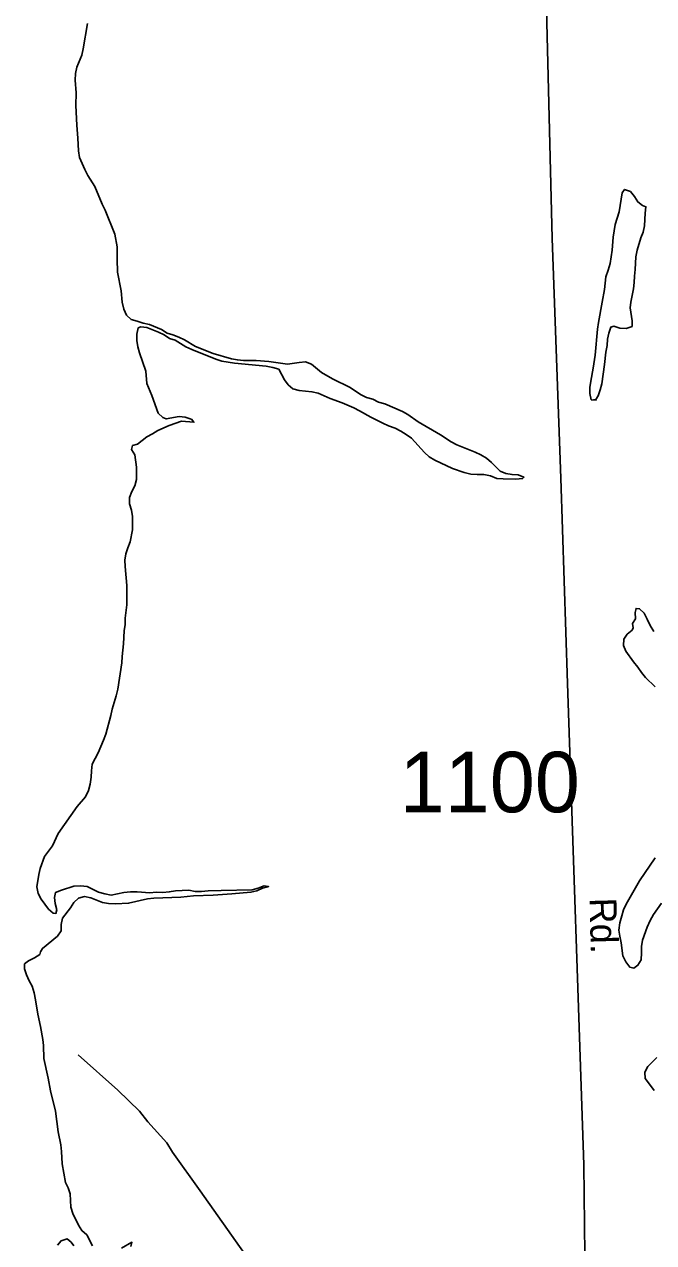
# Model space of a CAD drawing. Extents: x 1945482 to 2853149, y 66427 to 1015778.
# Drawn here: x 2325507 to 2327042, y 117706 to 120678 of the extents above; entities that cross this region are included whole.
import ezdxf

# ---------------------------------------------------------------- set-up
doc = ezdxf.new("R2010")
doc.units = 0
for name, color, linetype in [('Old_Level_11', 7, 'Continuous'), ('Old_Level_32', 7, 'Continuous'), ('Old_Level_35', 7, 'Continuous'), ('Old_Level_60', 7, 'Continuous'), ('Old_Level_8', 7, 'Continuous')]:
    doc.layers.add(name, color=color, linetype=linetype)

msp = doc.modelspace()

# ---------------------------------------------------------------- linework, layer by layer
at = {"layer": 'Old_Level_32'}
msp.add_lwpolyline([(2327467.5, 115613), (2327216.3, 115990), (2327054, 116232.6), (2327006.9, 116309.4), (2326966.8, 116386.2), (2326929.9, 116468.6), (2326914.2, 116526.2), (2326903.7, 116604.7), (2326893.2, 116772.3), (2326885.4, 117136.2), (2326877, 117384.2), (2326871.6, 117896.1), (2326831.4, 119069.9), (2326815.4, 119571.1), (2326794, 120155.3), (2326772.5, 121045)], dxfattribs=at)
at = {"layer": 'Old_Level_35'}
msp.add_lwpolyline([(2326978.1, 116346.6), (2326652.6, 116809.3), (2326394.8, 117178.8), (2326165.5, 117508.5), (2325936.1, 117832.3), (2325869, 117927.4), (2325854.7, 117949.5), (2325808.4, 118000.8), (2325788, 118026.9), (2325735.4, 118078.4), (2325638.5, 118164.1)], dxfattribs=at)
at = {"layer": 'Old_Level_60'}
for points in [[(2325767.7, 119957.9), (2325756.5, 119969), (2325750.2, 119983.1), (2325745.7, 120000), (2325743.2, 120028.2), (2325734.5, 120073.8), (2325733.5, 120104.9), (2325733.7, 120135.7), (2325727.7, 120166.2), (2325704.2, 120224.4), (2325697, 120239.1), (2325679, 120282.4), (2325662.2, 120309.7), (2325654.7, 120323.6), (2325641.5, 120353.3), (2325639.2, 120369.4), (2325637.7, 120400.4), (2325635, 120431.9), (2325633, 120479.7), (2325633.7, 120511), (2325631.5, 120542.1), (2325632, 120558.2), (2325635, 120573.3), (2325647.2, 120602.9), (2325651, 120618.6), (2325661.2, 120680.5)], [(2326902.2, 119761.2), (2326889.5, 119762.4), (2326886.5, 119777.2), (2326886.5, 119792.5), (2326888.2, 119807.9), (2326894.2, 119839.6), (2326899, 119871.3), (2326904.7, 119934.3), (2326907, 119950.7), (2326916.2, 120000), (2326921.5, 120031.3), (2326925.2, 120062.5), (2326931, 120078.1), (2326935.5, 120094.3), (2326940.5, 120127), (2326943.2, 120159.3), (2326948, 120189.8), (2326958, 120220.5), (2326964.7, 120267.1), (2326971, 120275.5), (2326985.2, 120270.1), (2326994.7, 120258.3), (2327003.2, 120245), (2327014.5, 120236.2), (2327023, 120233.1), (2327020.7, 120217.4), (2327019.7, 120186.5), (2327016.2, 120171.2), (2327010.7, 120157), (2327001.2, 120127), (2326998.2, 120111.1), (2326997, 120079.8), (2326994.7, 120064), (2326994.5, 120048.6), (2326993, 120033), (2326986, 120000), (2326984.2, 119986.6), (2326989.5, 119955), (2326989.2, 119941.3), (2326974.5, 119935.9), (2326959.2, 119936.7), (2326944.7, 119941.5), (2326937.2, 119939.6), (2326932.5, 119924.5), (2326929.2, 119909.8), (2326928, 119894.3), (2326925, 119878.6), (2326921.7, 119848.2), (2326915, 119801.2), (2326911.7, 119786.3), (2326906.5, 119772), (2326901, 119762.6), (2326895.5, 119762.5), (2326902.2, 119761.2)], [(2325577.5, 118509.9), (2325566, 118520), (2325548.5, 118544.5), (2325541, 118557.8), (2325537.7, 118573.9), (2325542.7, 118604.4), (2325546, 118619.1), (2325556.5, 118648.2), (2325575.7, 118673.9), (2325590, 118704.2), (2325636, 118769.9), (2325656.2, 118793.8), (2325663.5, 118808.9), (2325668, 118825), (2325670.7, 118841.5), (2325671, 118857.4), (2325673, 118873.4), (2325687.5, 118900.9), (2325700.7, 118931.6), (2325706, 118946.6), (2325718.5, 118992.1), (2325721.5, 119007.9), (2325731, 119039.9), (2325735, 119056.4), (2325745.5, 119120.9), (2325745.7, 119136.4), (2325749, 119167.2), (2325751, 119198.8), (2325753, 119214.3), (2325753.2, 119229.8), (2325757, 119261.9), (2325757, 119309.2), (2325753, 119355.6), (2325752.5, 119371), (2325755, 119386.3), (2325759.7, 119401.2), (2325765.7, 119415.4), (2325771, 119445.4), (2325771, 119477.7), (2325768.7, 119493), (2325764, 119508.6), (2325764, 119524.3), (2325769.5, 119538.5), (2325777, 119552.1), (2325780.7, 119567.5), (2325780.5, 119598), (2325777.2, 119627.8), (2325768.7, 119640.9), (2325771.5, 119650.4), (2325783.5, 119654), (2325806.2, 119672.1), (2325819.7, 119679.1), (2325832.5, 119687.7), (2325860.5, 119699.8), (2325890.2, 119709.7), (2325921, 119707.5), (2325914.7, 119714.6), (2325914.2, 119715.1), (2325899.7, 119719.8), (2325884.5, 119721.3), (2325853.5, 119715.7), (2325845, 119718.9), (2325834, 119729.8), (2325818.5, 119772.9), (2325806.2, 119801.7), (2325803.5, 119832.2), (2325788.5, 119876.8), (2325784.5, 119891.3), (2325782, 119906.8), (2325781.5, 119922.5), (2325785, 119937.4), (2325791.2, 119939.9)], [(2325767.7, 119957.9), (2325782.8, 119954.3), (2325797.5, 119949.4), (2325812.5, 119946.2), (2325841.5, 119933.3), (2325855.5, 119925.1), (2325869.7, 119920.5), (2325883.7, 119914.8), (2325897.5, 119908.1), (2325924.5, 119892.1), (2325967.7, 119874.9), (2326012.2, 119862.2), (2326027, 119859.5), (2326042, 119858.4), (2326072.7, 119858.4), (2326103.7, 119855.5), (2326149, 119848.9), (2326177.7, 119853.4), (2326192.7, 119854.9), (2326207.2, 119848.8), (2326231.7, 119828.6), (2326258.5, 119813.1), (2326301.7, 119792.6), (2326327, 119774.9), (2326341.7, 119767.8), (2326356.7, 119763.8), (2326371.2, 119756.8), (2326386, 119752.2), (2326429, 119733.6), (2326442.7, 119726.7), (2326467.5, 119708.3), (2326521.7, 119677), (2326548.2, 119659.4), (2326562, 119652.1), (2326606.2, 119634.5), (2326620.7, 119627.7), (2326634, 119619.7), (2326646, 119609.3), (2326667.5, 119587.9), (2326681.7, 119582.7), (2326696.5, 119579.7), (2326711.5, 119579.5), (2326725.5, 119573.2), (2326724, 119571.9), (2326722, 119570.2), (2326705.7, 119568.6), (2326674.7, 119569.2), (2326659, 119570.3), (2326644, 119576.5), (2326628, 119579.9), (2326611.7, 119579.9), (2326596, 119580.9), (2326580, 119585), (2326551.2, 119594.6), (2326508, 119614.7), (2326494.5, 119622.9), (2326483, 119633.4), (2326451, 119668.8), (2326438.7, 119677.6), (2326425, 119686.1), (2326411.5, 119693), (2326395.5, 119698.8), (2326381.2, 119705.6), (2326352.5, 119719.8), (2326324.5, 119735.7), (2326310.5, 119742.8), (2326282.2, 119755), (2326253, 119765.3), (2326224, 119778.3), (2326208.5, 119782), (2326177.2, 119784.8), (2326162, 119788.7), (2326151, 119798.9), (2326141.5, 119811.2), (2326127.7, 119836.8), (2326113, 119841.3), (2326097, 119844.3), (2326019.5, 119851.7), (2325989.2, 119856.5), (2325974, 119861), (2325915.5, 119884.9), (2325901.5, 119891.5), (2325875.5, 119907.6), (2325861, 119911.6), (2325848.5, 119920.3), (2325834.5, 119927.2), (2325806.2, 119938.9), (2325791.2, 119939.9)], [(2327045.7, 119062.1), (2327022.2, 119085.2), (2327012.2, 119097.3), (2327003.5, 119110), (2326993, 119122.7), (2326973.7, 119149.1), (2326968.2, 119163.2), (2326969, 119178.4), (2326977.2, 119190.5), (2326989, 119200.5), (2326991.5, 119205.9), (2326990.2, 119216.8), (2326997.5, 119228.3), (2326997, 119243.5), (2326999, 119253.3), (2327007.5, 119252.4), (2327018.5, 119241.9), (2327026.2, 119227.1), (2327033, 119211.8), (2327042, 119197)], [(2326993.5, 118375.5), (2326983.5, 118378.4), (2326974, 118391.3), (2326966.7, 118406.2), (2326962.7, 118437.9), (2326959, 118453.5), (2326957, 118468.6), (2326959.5, 118486), (2326964, 118503.1), (2326968.5, 118518), (2326974.5, 118532.1), (2327007.5, 118588.9), (2327045.5, 118645.1)], [(2325577.5, 118509.9), (2325584, 118509.1), (2325586.5, 118518.5), (2325582.2, 118533.5), (2325580.7, 118548.6), (2325583.5, 118560.4), (2325597.7, 118566.4), (2325628.2, 118575.7), (2325644, 118576.6), (2325660.5, 118574.8), (2325688.5, 118561.6), (2325704, 118557.3), (2325719.2, 118554.2), (2325750, 118560.1), (2325766.5, 118562.3), (2325782.2, 118562.1), (2325813.5, 118559.5), (2325828.7, 118560.8), (2325845, 118560.4), (2325860.7, 118562), (2325876.2, 118564.7), (2325908.2, 118565.8), (2325924, 118562.8), (2325939, 118562.5), (2325955.2, 118564.2), (2325987, 118565.5), (2326063, 118566.7), (2326077.7, 118571), (2326092, 118576.3), (2326102.7, 118575), (2326100.5, 118574.4), (2326088, 118571), (2326074.5, 118564.1), (2326060, 118561), (2326013.5, 118557.1), (2325967.5, 118554.1), (2325920, 118552.1), (2325889, 118549.3), (2325823, 118546.6), (2325808, 118544.7), (2325761.5, 118534.1), (2325729.5, 118533), (2325713, 118533.8), (2325698, 118536.3), (2325669.2, 118547.7), (2325654, 118550.8), (2325639.2, 118546.4), (2325627.7, 118536.1), (2325620.2, 118523), (2325600.5, 118498.1), (2325597.2, 118482.5), (2325597, 118466.9), (2325588, 118454.2), (2325551.7, 118424.2), (2325547, 118415.9), (2325545.2, 118409.2), (2325532, 118400.8), (2325517.5, 118393.9), (2325507.5, 118386.1)], [(2327060.5, 118534.2), (2327041.5, 118506.9), (2327033.2, 118492), (2327026.2, 118476.2), (2327014.5, 118444.4), (2327012.2, 118429), (2327012.5, 118412.9), (2327011.5, 118396.5), (2327003.5, 118383), (2326993.5, 118375.5)], [(2325552.5, 118202.1), (2325547.2, 118233.7), (2325540.5, 118263.6), (2325534.7, 118298.4), (2325531, 118315.3), (2325526.5, 118331.6), (2325519.2, 118345.3), (2325513, 118359.8), (2325508.2, 118374.4), (2325507.5, 118386.1)], [(2325673.7, 117698.6), (2325659.7, 117725.4), (2325647.7, 117735.7), (2325639.5, 117748.7), (2325626, 117777.2), (2325621, 117793.1), (2325619.5, 117825.5), (2325614, 117839.6), (2325607.5, 117853.3), (2325599.7, 117898.5), (2325598.2, 117928.5), (2325596, 117944.7), (2325590, 117976.2), (2325583, 118027.3), (2325571, 118076.3), (2325565.7, 118107.5), (2325555.2, 118155.7), (2325554, 118186.9), (2325552.5, 118202.1)], [(2327043, 118077.7), (2327029.5, 118096), (2327021, 118107.1), (2327020.2, 118122.2), (2327027.5, 118136), (2327049.5, 118158.2)], [(2325588, 117700.4), (2325597, 117710.4), (2325612.2, 117715.8), (2325621.5, 117707.4), (2325628.2, 117698.5)], [(2325767, 117697.1), (2325769.7, 117707.2), (2325744.5, 117693)]]:
    msp.add_lwpolyline(points, dxfattribs=at)

# ---------------------------------------------------------------- texts
at = {"layer": 'Old_Level_11'}
msp.add_text('Rd.', height=65.62, rotation=271.5286, dxfattribs=at).set_placement((2326885.2, 118546.9))
at = {"layer": 'Old_Level_8'}
msp.add_text('1100', height=147.64, dxfattribs=at).set_placement((2326422.6, 118756))

doc.saveas('drawing.dxf')
